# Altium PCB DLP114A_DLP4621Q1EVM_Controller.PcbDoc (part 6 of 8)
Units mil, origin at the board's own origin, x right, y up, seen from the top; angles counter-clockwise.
Board outline 4803.15 x 2598.43 mil, 14 copper layers (Top Layer, GND 1, SIGNAL 1, GND 2, SIGNAL 2, PWR SPLIT PLANE 1, GND 3, GND 4, PWR SPLIT PLANE 2, SIGNAL 3, GND 5, SIGNAL 4, GND 6, Bottom Layer), stack 91.4 mil thick; 489 components, 394 nets, 1925 pads, 1273 vias.
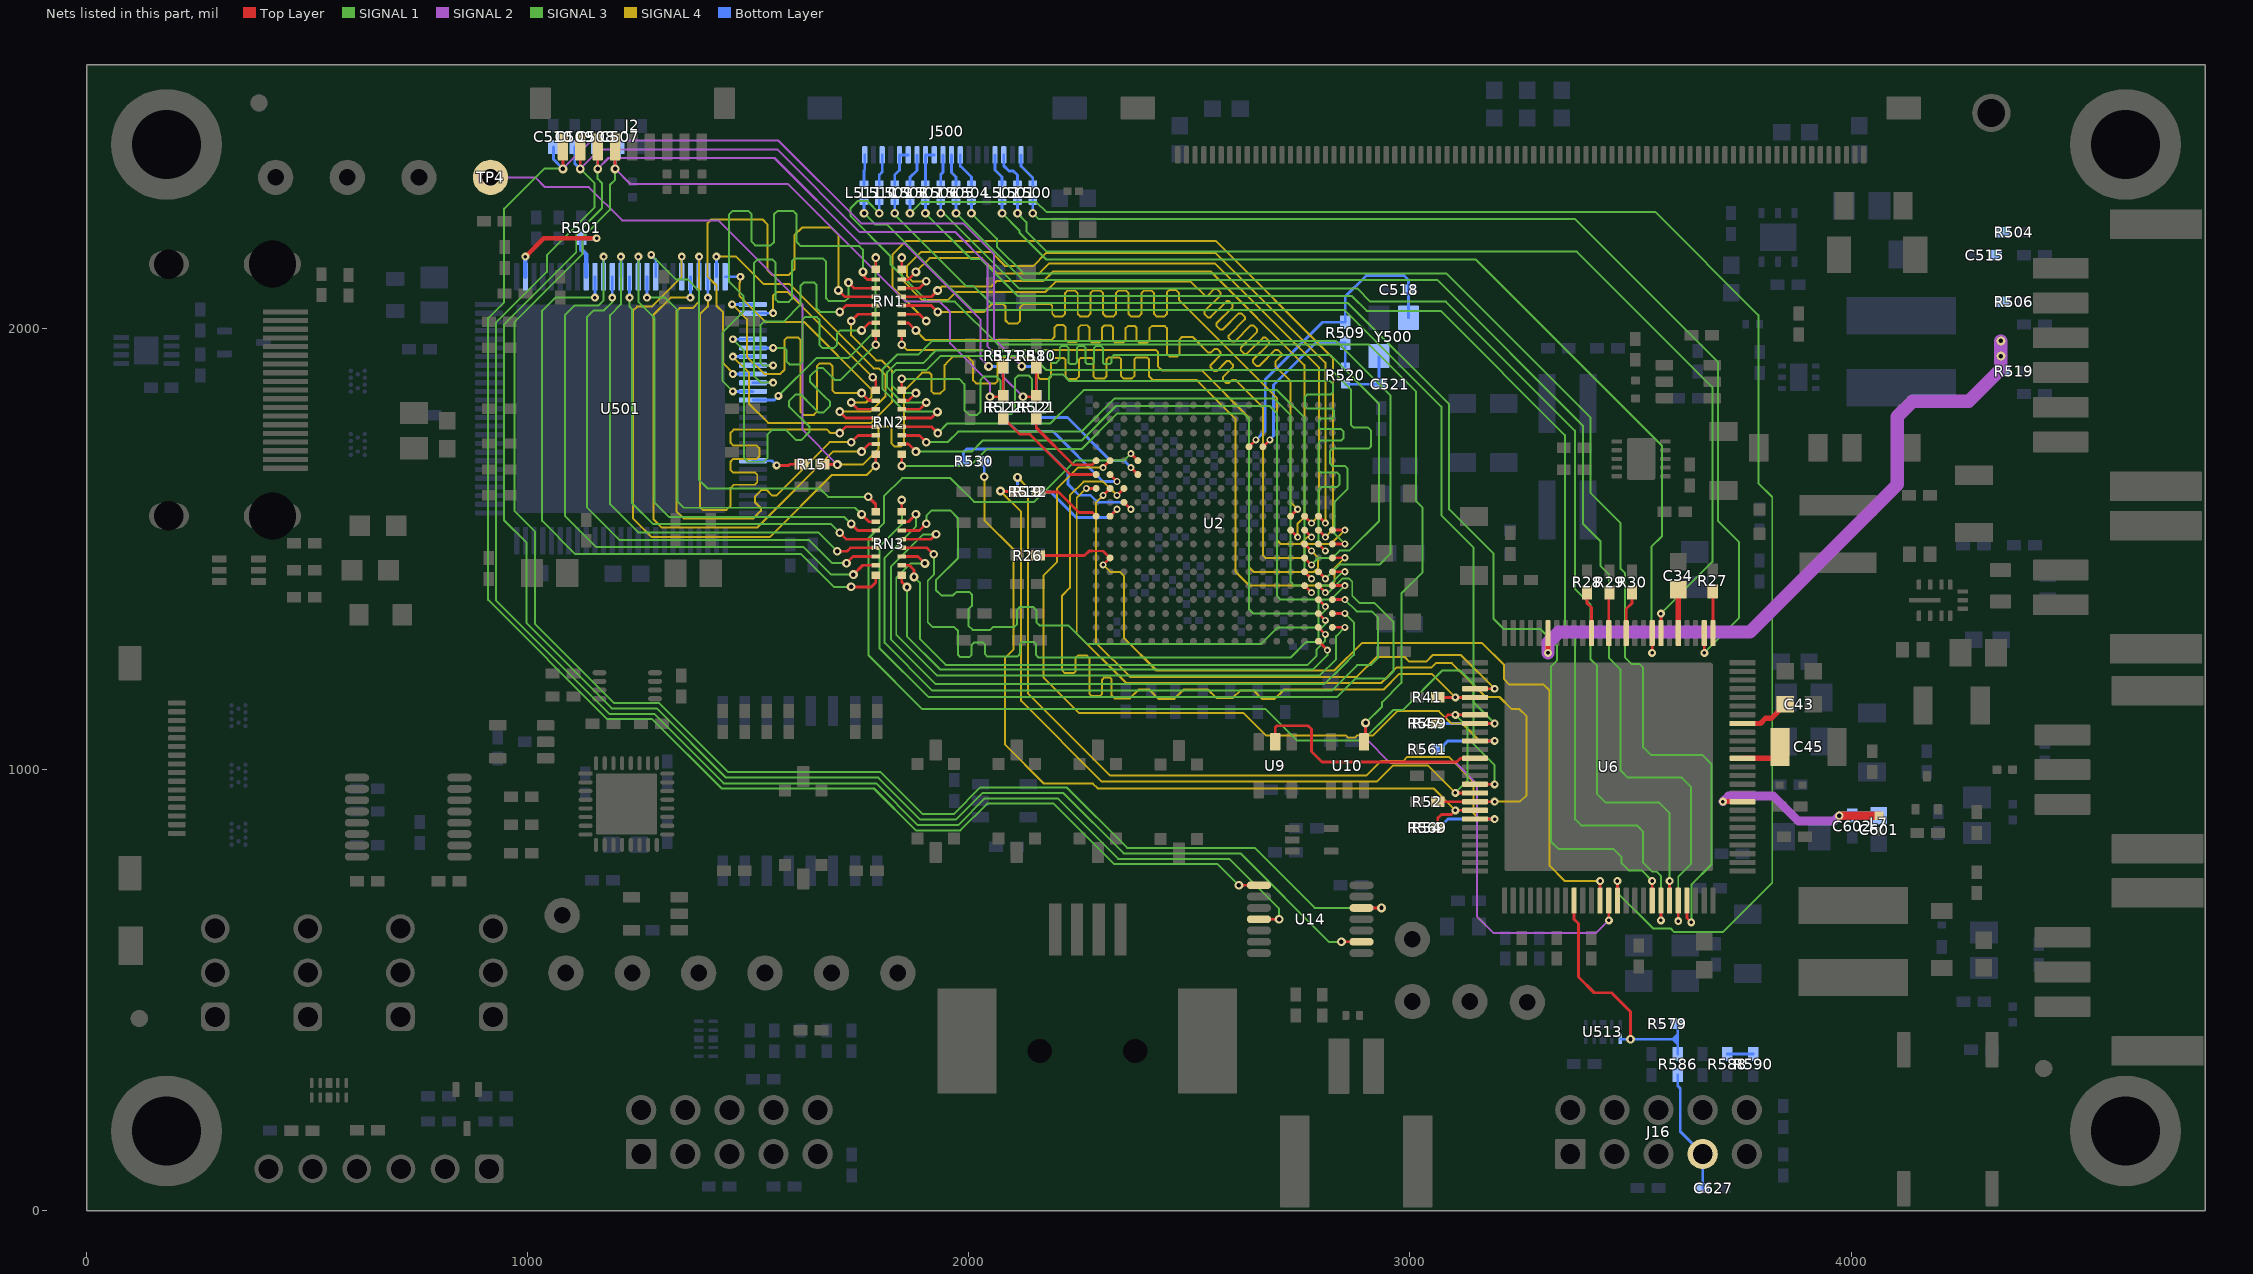
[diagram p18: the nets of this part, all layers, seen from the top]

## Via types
v1: diameter 20, hole 10, Top Layer to Bottom Layer, tented top, 716 vias
v2: diameter 16, hole 8, Top Layer to Bottom Layer, 234 vias
v3: diameter 19.68, hole 7.87, Top Layer to Bottom Layer, 170 vias
v4: diameter 18, hole 8, Top Layer to Bottom Layer, tented top, 78 vias
v5: diameter 18, hole 8, Top Layer to Bottom Layer, tented bottom, 51 vias
v6: diameter 39.37, hole 19.68, Top Layer to Bottom Layer, 24 vias

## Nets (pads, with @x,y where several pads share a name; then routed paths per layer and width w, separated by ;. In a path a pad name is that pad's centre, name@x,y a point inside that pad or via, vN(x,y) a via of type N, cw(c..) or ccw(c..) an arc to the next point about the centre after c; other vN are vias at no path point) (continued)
PCLK: R15.2 TP4.1 U2.M18 | length 3706.6
  Top Layer w6.3: R15.2@1667.85,1692.37 1668.18,1692.04 1701.77,1692.04 v1(1702.1,1691.71) ; U2.M18@2824.17,1480.31 v2@2852.33,1480.31
  SIGNAL 4 w4.5: v1(1702.1,1691.71) 1759.51,1691.71 1794.76,1726.96 1794.76,1773.77 1799.44,1778.45 1821.7,1778.45 1825.11,1775.05 1825.11,1738.96 1831.71,1732.35 1845.94,1732.35 1852.43,1738.84 1852.43,1858.4 1894.14,1900.11 1910.66,1900.11 1914.88,1895.89 1914.88,1858.36 1920.21,1853.03 1935.52,1853.03 1944.86,1862.37 1944.86,1917.34 1952.43,1924.91 1963.98,1936.46 1997.13,1936.46 2002.72,1930.87 2009.63,1923.97 2009.63,1882.65 2016.57,1875.71 2050.69,1875.71 2060.24,1875.71 2065.21,1880.68 2065.21,1924.65 2074.88,1934.32 2150.85,1934.32 2152.79,1932.38 2156.45,1928.72 2156.45,1890.36 2161.47,1885.34 2180.91,1885.34 2186.22,1890.66 2186.22,1928.83 2190.31,1932.92 2215.72,1932.92 2219.38,1929.26 2219.38,1890.9 2224.39,1885.89 2243.84,1885.89 2249.15,1891.2 2249.15,1929.37 2253.24,1933.46 2278.64,1933.46 2282.3,1929.8 2282.3,1891.44 2287.32,1886.43 2306.77,1886.43 2312.08,1891.74 2312.08,1929.91 2316.17,1934 2341.57,1934 2345.23,1930.34 2345.23,1891.98 2350.25,1886.97 2369.69,1886.97 2375,1892.28 2375,1930.45 2379.09,1934.54 2404.5,1934.54 2408.16,1930.89 2408.16,1892.52 2417.49,1883.19 2516.83,1883.19 2518.05,1881.97 2603.97,1796.05 2603.97,1449.35 2636.16,1417.16 2819.43,1417.16 2829.38,1427.11 2829.38,1457.34 v2(2852.49,1480.48)
  SIGNAL 2 w4.5: TP4.1@915.73,2342.8 1017.24,2342.8 1039.18,2320.86 1138.56,2320.86 1214.12,2245.3 1431.9,2245.3 1622.97,2054.23 1622.97,1770.84 v1(1702.1,1691.71)
PCLK_S: R15.1 U501.44 | length 115.4
  Top Layer w6.3: v5(1564.12,1689.81) 1592.46,1689.81 1595.02,1692.37 R15.1@1620.61,1692.37
  Bottom Layer w6.3: U501.44@1510.53,1700.21 1553.72,1700.21 v5(1564.12,1689.81)
PDATA0: RN3.9 U2.V17 | length 1180.5
  Top Layer w6.3: RN3.9@1847.91,1440.45 1847.91,1425.89 v1(1859.71,1414.09) ; U2.V17@2792.51,1291.17 v2(2812.56,1271.12)
  SIGNAL 1 w4.5: v1@1859.39,1413.77 1859.39,1302.96 1935.71,1226.64 2779.79,1226.64 2812.56,1259.41 v2(2812.56,1271.12)
PDATA1: RN3.10 U2.U17 | length 1205.5
  Top Layer w6.3: RN3.10@1847.91,1463.51 1865.11,1463.51 1875.63,1452.99 v1(1875.63,1437.04) ; U2.U17@2792.51,1322.67 v2(2808.26,1306.9)
  SIGNAL 1 w4.5: v1(1875.63,1437.04) 1888.79,1423.87 1888.79,1296.64 1947.54,1237.89 2768.19,1237.89 2788.4,1258.09 2788.4,1273.03 2807.52,1292.15 2807.52,1306.16 v2(2808.26,1306.9)
PDATA2: RN3.11 U2.U18 | length 1426.2
  Top Layer w6.3: RN3.11@1847.91,1483.27 1884.76,1483.27 v1(1900.33,1467.7) ; U2.U18@2824.13,1322.79 v2(2852.49,1322.79)
  SIGNAL 1 w4.5: v1(1900.33,1467.7) 1867.85,1467.7 1835.42,1435.27 1835.42,1305.48 1927.22,1213.69 2795.49,1213.69 2832.53,1250.73 2832.53,1302.84 v2(2852.49,1322.79)
PDATA3: RN3.12 U2.T17 | length 1385.3
  Top Layer w6.3: RN3.12@1847.91,1502.95 1905.5,1502.95 v1@1920.09,1488.37 ; U2.T17@2792.51,1354.16 v2(2808.26,1338.42)
  SIGNAL 1 w4.5: v1(1920.45,1488.37) 1920.45,1442.37 1906.81,1428.73 1906.81,1334.37 1917.32,1323.86 1966.13,1323.86 1975.59,1314.4 1975.59,1260.09 1980.67,1255.01 2000.89,1255.01 2006.31,1260.42 2006.31,1282.76 2012.13,1288.58 2030.91,1288.58 2036.71,1282.79 2036.71,1261.73 2042.06,1256.38 2109.97,1256.38 2115.85,1262.26 2115.85,1284.56 2121.28,1289.98 2147.12,1289.98 2152.29,1284.82 2152.29,1259.74 2157.92,1254.11 2729.1,1254.11 2764.01,1289.01 2784.31,1289.01 2792.42,1297.12 2792.42,1314.25 2808.26,1330.08 v2(2808.26,1338.42)
PDATA4: RN3.13 U2.T18 | length 1629
  Top Layer w6.3: RN3.13@1847.91,1522.64 1914.83,1522.64 v1@1925.71,1533.51 ; U2.T18@2824.13,1354.29 v2(2852.49,1354.29)
  SIGNAL 1 w4.5: v1(1925.77,1533.58) 1925.64,1533.45 1896.27,1533.45 1823.86,1461.04 1823.86,1294.73 1924.23,1194.36 2806.6,1194.36 2848.47,1236.24 2872.75,1260.51 2872.75,1334.03 v2(2852.49,1354.29)
PDATA5: RN3.14 U2.R17 | length 1489.9
  Top Layer w6.3: RN3.14@1847.91,1542.32 1888.08,1542.32 v1(1903.53,1557.77) ; U2.R17@2792.51,1385.66 v2(2808.26,1369.91)
  SIGNAL 1 w4.5: v1(1903.53,1557.77) 1903.53,1575.8 1915.58,1587.85 1957.4,1587.85 1975.4,1569.84 1975.4,1479.39 1925.3,1429.28 1925.3,1407.35 1937.56,1395.09 1964.1,1395.09 1972.33,1403.31 2000.83,1403.31 2006.94,1397.2 2006.94,1371.5 1998.96,1363.52 1998.96,1326.41 2008.44,1316.93 2048.3,1316.93 2055.19,1323.81 2103.39,1323.81 2109.68,1330.1 2109.68,1362.57 2115.95,1368.83 2146.1,1368.83 2153.01,1361.92 2153.01,1334.4 2160.1,1327.31 2225.62,1327.31 2267.49,1285.44 2663.08,1285.44 2700.52,1322.87 2784.89,1322.87 2792.51,1330.49 2792.51,1345.94 2808.26,1361.69 v2(2808.26,1369.91)
PDATA6: RN3.15 U2.R18 | length 1765.1
  Top Layer w6.3: RN3.15@1847.91,1562.01 1862.8,1562.01 v1(1879.83,1579.04) ; U2.R18@2824.13,1385.79 v2(2852.49,1385.79)
  SIGNAL 1 w4.5: v1@1879.94,1578.94 1879.94,1551.14 1809.17,1480.38 1809.17,1287.53 1917.37,1179.33 2822.52,1179.33 2880.15,1236.96 2911.29,1236.96 2927.1,1252.77 2927.1,1345.34 2913.62,1358.82 2879.31,1358.82 v2@2852.49,1385.63
PDATA7: RN3.16 U2.P17 | length 1979.6
  Top Layer w6.3: RN3.16@1847.91,1585.14 v1(1847.91,1611.51) ; U2.P17@2792.51,1417.16 v2(2808.26,1401.41)
  SIGNAL 1 w4.5: v1(1847.91,1611.51) 1847.91,1556.1 1797.23,1505.42 1797.23,1275.96 1908.89,1164.3 2833.58,1164.3 2875.94,1206.65 2946.27,1206.65 2962.26,1222.64 2962.26,1335.55 2919.37,1378.44 2885.07,1378.44 2879.39,1384.11 2869.13,1394.38 2869.13,1426.11 2862.22,1433.03 2846.56,1433.03 2814.93,1401.41 v2(2808.26,1401.41)
PDATA8: RN2.9 U2.P18 | length 1583.7
  Top Layer w6.3: v1(1847.91,1688.76) RN2.9@1847.91,1715.12 ; U2.P18@2824.13,1417.28 v2(2852.49,1417.28)
  SIGNAL 1 w4.5: v1@1848.08,1688.93 2003.27,1688.93 2041.02,1726.68 2229.36,1726.68 2255.32,1726.68 2336.22,1807.58 2622.51,1807.58 2635.03,1795.06 2635.03,1364.09 2644.96,1354.16 2786.56,1354.16 2792.51,1360.12 2792.51,1375.85 2802.32,1385.66 2820.68,1385.66 v2@2852.31,1417.28
PDATA9: RN2.10 U2.N18 | length 1544.5
  Top Layer w6.3: RN2.10@1847.91,1738.25 1862.8,1738.25 v1(1879.83,1721.22) ; U2.N18@2824.13,1448.78 v2(2852.49,1448.78)
  SIGNAL 1 w4.5: v1(1879.83,1721.22) 2006.46,1721.22 2031.56,1746.32 2229.36,1746.32 2255.47,1746.32 2333.61,1824.47 2682.19,1824.47 2698.02,1808.64 2698.02,1394.85 2707.21,1385.66 2786.56,1385.66 2792.51,1391.61 2792.51,1411.2 2798.51,1417.2 2815.71,1417.2 2847.29,1448.78 v2(2852.49,1448.78)
PDATA10: RN2.11 U2.P16 | length 1402.1
  Top Layer w6.3: RN2.11@1847.91,1757.94 1888.08,1757.94 v1(1903.53,1742.49) ; U2.P16@2761.01,1417.16 v2(2776.76,1401.41)
  SIGNAL 1 w4.5: v1(1903.53,1742.49) 1951.54,1742.49 1975.68,1766.64 2229.36,1766.64 2255.38,1766.64 2330.51,1841.77 2690.81,1841.77 2729.52,1803.05 2729.52,1425.69 2738,1417.21 2760.96,1417.21 v2(2776.76,1401.41)
PDATA11: RN2.12 U2.N16 | length 1379.3
  Top Layer w6.3: RN2.12@1847.91,1777.62 1914.83,1777.62 v1(1929.42,1763.04) ; U2.N16@2761.01,1448.65 v2(2776.76,1432.9)
  SIGNAL 1 w4.5: v1(1929.42,1763.04) 1951.19,1784.81 2184.28,1784.81 2229.36,1829.88 2259.95,1860.48 2698.51,1860.48 2761.01,1797.97 2761.01,1448.65 v2(2776.76,1432.9)
PDATA12: RN2.13 U2.N17 | length 2058.3
  Top Layer w6.3: RN2.13@1847.91,1797.31 1914.83,1797.31 v1(1928.68,1811.16) ; U2.N17@2792.51,1448.65 v2(2808.26,1432.9)
  SIGNAL 1 w4.5: v1(1928.68,1811.16) 1927.94,1811.9 1855.24,1811.9 1804.56,1862.57 1804.56,1908.36 1837.09,1940.88 1885.4,1940.88 1916.14,1971.63 2832.6,1971.63 2955.74,1848.48 2955.74,1489.47 2931.5,1465.23 2840.58,1465.23 v2(2808.26,1432.9)
PDATA13: RN2.14 U2.M16 | length 2122.9
  Top Layer w6.3: RN2.14@1847.91,1816.99 1888.08,1816.99 v1(1903.53,1832.44) ; U2.M16@2761.01,1480.15 v2(2776.76,1464.4)
  SIGNAL 1 w4.5: v1(1903.53,1832.44) 1849.4,1832.44 1814.96,1866.88 1814.96,1901.26 1836.1,1922.39 1897.41,1922.39 1925.49,1950.48 2176.86,1950.48 2183.66,1943.67 2183.66,1927.75 2189.02,1922.39 2198.38,1922.39 2206.06,1930.07 2206.06,1956.09 2209.96,1959.99 2221.66,1959.99 2225.56,1956.09 2225.56,1923.17 2229.46,1919.27 2241.16,1919.27 2245.06,1923.17 2245.06,1956.09 2248.96,1959.99 2260.66,1959.99 2264.56,1956.09 2264.56,1923.17 2268.46,1919.27 2280.16,1919.27 2284.06,1923.17 2284.06,1956.09 2287.96,1959.99 2299.66,1959.99 2303.56,1956.09 2303.56,1923.17 2307.46,1919.27 2319.16,1919.27 2323.06,1923.17 2323.06,1934.32 2328.32,1939.58 2374.09,1939.58 ; 2387.23,1939.58 2374.09,1939.58 ; v2(2776.76,1464.4) 2792.35,1479.99 2823.85,1479.99 2840.38,1496.52 2862.5,1496.52 2929.73,1563.75 2929.73,1829.75 2819.9,1939.58 2374.09,1939.58
PDATA14: RN2.15 U2.L18 | length 1774.7
  Top Layer w6.3: RN2.15@1847.91,1836.68 1862.8,1836.68 v1(1879.83,1853.71) ; U2.L18@2824.13,1511.77 v2(2852.49,1511.77)
  SIGNAL 1 w4.5: v1(1879.83,1853.71) 1843.64,1853.71 1825.48,1871.88 1825.48,1897.05 1834.79,1906.36 1904.16,1906.36 1935.2,1937.41 2143.84,1937.41 2174.88,1906.36 2184.93,1906.36 ; 2184.95,1906.38 2217.22,1906.38 ; 2217.23,1906.36 2821.71,1906.36 2865.95,1862.12 2865.95,1781.83 2872.4,1775.38 2905.28,1775.38 2912.08,1768.58 2912.08,1733.79 2906.19,1727.9 2823.81,1727.9 2818.24,1722.33 2818.24,1694.26 2823.48,1689.01 2852.01,1689.01 2858.75,1682.28 2858.75,1636.48 2828.4,1606.14 2828.4,1535.86 v2(2852.49,1511.77)
PDATA15: RN2.16 U2.L17 | length 2202.8
  Top Layer w6.3: RN2.16@1847.91,1859.81 v1(1847.91,1886.18) ; U2.L17@2792.51,1511.64 v2(2808.26,1495.9)
  SIGNAL 1 w4.5: v1(1847.91,1886.18) 1939.27,1886.18 1977.82,1886.18 1989.99,1874 1989.99,1815.3 2001.04,1804.24 2018.9,1804.24 2026.67,1812.01 2026.67,1883.84 2034.24,1891.42 2062.43,1891.42 2071.9,1881.95 2071.9,1812.62 2077.74,1806.77 2096.65,1806.77 2104.17,1814.29 2104.17,1886.12 2111.75,1893.7 2135.41,1893.7 2142.92,1886.18 2142.92,1816.63 2150.5,1809.05 2174.16,1809.05 2181.68,1816.57 2181.68,1888.4 2189.25,1895.98 2212.91,1895.98 2228.13,1880.76 2818.89,1880.76 2825.2,1874.45 2825.2,1855.85 2819.86,1850.51 2766.96,1850.51 2762.28,1845.83 2762.28,1823.8 2767.46,1818.62 2823.45,1818.62 2827.45,1814.61 2827.45,1799.48 2823.78,1795.81 2797.47,1795.81 2793.53,1791.87 2793.53,1776.53 2797.97,1772.09 2843.93,1772.09 2849.09,1766.93 2849.09,1751.29 2844.31,1746.51 2798.28,1746.51 2792.32,1740.54 2792.32,1679.63 2797.73,1674.21 2834.16,1674.21 2839.91,1668.46 2839.91,1646.09 2834.43,1640.61 2798.32,1640.61 2792.32,1634.61 2792.32,1511.84 v2(2808.26,1495.9)
PDATA16: RN1.9 U2.L16 | length 1471.8
  Top Layer w6.3: v1(1847.91,1963.43) RN1.9@1847.91,1989.79 ; U2.L16@2761.01,1511.64 v2(2776.76,1495.9)
  SIGNAL 4 w4.5: v1(1847.91,1963.43) 1859.57,1951.72 2423.65,1951.72 2429.25,1946.11 2429.25,1913.97 2437.83,1905.39 2527.49,1905.39 2635.03,1797.85 2635.03,1458.58 2645.27,1448.34 2782.27,1448.34 2792.01,1458.08 2792.01,1480.65 v2(2776.76,1495.9)
PDATA17: RN1.10 U2.K18 | length 2012.4
  Top Layer w6.3: RN1.10@1847.91,2012.92 1862.8,2012.92 v1(1879.83,1995.89) ; U2.K18@2824.13,1543.27 v2(2852.49,1543.27)
  SIGNAL 4 w4.5: v1(1879.83,1995.89) 1901.69,1974.03 2186.54,1974.03 2194.52,1982.01 2194.52,2002.61 2200.05,2008.14 2214.48,2008.14 2219.54,2003.08 2219.54,1974.43 2224.81,1969.17 2243.01,1969.17 2248.19,1974.34 2248.19,2002.02 2253.72,2007.55 2268.14,2007.55 2273.2,2002.49 2273.2,1973.84 2278.47,1968.58 2296.67,1968.58 2301.85,1973.75 2301.85,2001.43 2307.38,2006.96 2321.8,2006.96 2326.87,2001.9 2326.87,1973.25 2332.14,1967.99 2350.33,1967.99 2355.51,1973.16 2355.51,2000.84 2361.04,2006.37 2375.46,2006.37 2380.53,2001.31 2380.53,1972.66 2385.8,1967.4 2404,1967.4 2409.17,1972.57 2409.17,2000.25 2414.7,2005.78 2444.12,2005.78 2449.19,2000.72 2449.19,1942.07 2454.46,1936.81 2472.66,1936.81 2477.83,1941.98 2477.83,1975.57 2483.16,1980.9 2507.52,1980.9 2542.98,1945.44 2548.49,1945.44 2557.12,1954.06 2562.64,1954.06 2570.91,1945.79 2570.91,1940.28 2548.14,1917.51 2548.14,1911.99 2556.41,1903.72 2561.93,1903.72 2584.7,1926.49 2590.21,1926.49 2598.49,1918.21 2598.49,1912.7 2575.72,1889.93 2575.72,1884.41 2583.99,1876.14 2589.51,1876.14 2596.71,1883.34 2605.07,1883.34 2666.52,1821.9 2666.52,1485.99 2672.35,1480.15 2754.79,1480.15 2761.01,1486.37 2761.01,1503.19 2769.47,1511.64 2820.87,1511.64 v2(2852.49,1543.27)
PDATA18: RN1.11 U2.K17 | length 1801.2
  Top Layer w6.3: RN1.11@1847.91,2032.61 1888.08,2032.61 v1(1903.53,2017.16) ; U2.K17@2792.51,1543.14 v2(2808.26,1527.39)
  SIGNAL 4 w4.5: v1(1903.53,2017.16) 1827.02,2093.67 1827.02,2168.24 1857.7,2198.92 2559.8,2198.92 2825.39,1933.33 2825.39,1881.97 2825.39,1544.52 v2(2808.26,1527.39)
PDATA19: RN1.12 U2.K16 | length 1970.7
  Top Layer w6.3: RN1.12@1847.91,2052.29 1914.83,2052.29 v1(1929.42,2037.7) ; U2.K16@2761.01,1543.14 v2(2776.76,1527.39)
  SIGNAL 4 w4.5: v1(1929.42,2037.7) 1958.06,2037.7 2034.3,2037.7 2052.02,2055.43 2078.06,2055.43 2083.11,2050.37 2083.11,2018.34 2090.3,2011.15 2109.7,2011.15 2115.58,2017.03 2115.58,2047.14 2122.63,2054.2 2124.29,2055.85 2184.69,2055.85 2189.04,2051.5 2189.04,2033.25 ; 2189.04,2033.18 2194.35,2027.87 2212.76,2027.87 2218.01,2033.12 ; 2218.01,2033.2 2218.01,2080.53 ; 2218.01,2080.68 2218.01,2080.53 ; 2246.86,2033.05 2252.04,2027.87 2270.45,2027.87 2275.7,2033.12 ; 2246.86,2033.12 2246.86,2080.6 2241.68,2085.78 2223.27,2085.78 2218.01,2080.53 ; 2275.7,2033.2 2275.7,2080.53 ; 2275.7,2080.68 2275.7,2080.53 ; 2304.54,2033.05 2309.72,2027.87 2328.14,2027.87 2333.39,2033.12 ; 2304.54,2033.12 2304.54,2080.6 2299.37,2085.78 2280.95,2085.78 2275.7,2080.53 ; 2333.39,2033.2 2333.39,2080.53 ; 2333.39,2080.68 2333.39,2080.53 ; 2362.23,2033.05 2367.41,2027.87 2385.82,2027.87 2391.07,2033.12 ; 2362.23,2033.12 2362.23,2080.6 2357.05,2085.78 2338.64,2085.78 2333.39,2080.53 ; 2391.07,2033.2 2391.07,2080.53 2396.33,2085.78 2414.74,2085.78 2419.92,2080.6 2419.92,2033.12 2425.17,2027.87 2443.58,2027.87 2448.76,2033.05 2448.76,2082.3 2453.67,2087.21 2469.77,2087.21 2476.03,2080.95 2476.03,2065.16 2659.21,1881.97 2698.02,1843.16 2698.02,1520.9 2707.27,1511.64 2751.65,1511.64 2767.4,1527.39 v2(2776.76,1527.39)
PDATA20: RN1.13 U2.K15 | length 1442.7
  Top Layer w6.3: RN1.13@1847.91,2071.98 1914.83,2071.98 v1(1929.23,2086.38) ; U2.K15@2729.52,1543.14 v2(2745.27,1527.39)
  SIGNAL 4 w4.5: v1(1929.23,2086.38) 1938.21,2095.36 2050.47,2095.36 2062.63,2107.52 2169.15,2107.52 2191.01,2129.38 2548.37,2129.38 2760.62,1917.12 2760.62,1881.97 2760.62,1572.69 2745.06,1557.13 v2@2745.06,1527.6
PDATA21: RN1.14 U2.J17 | length 1609.6
  Top Layer w6.3: RN1.14@1847.91,2091.66 1888.08,2091.66 v1(1903.53,2107.11) ; U2.J17@2792.51,1574.64 v2(2808.26,1558.89)
  SIGNAL 4 w4.5: v1(1903.53,2107.11) 1871.92,2107.11 1859.6,2119.43 1859.6,2141.54 1892.08,2174.02 2050.66,2174.02 2083.07,2141.6 2145.55,2141.6 2174.78,2170.83 2560.09,2170.83 2808.26,1922.66 2808.26,1881.97 v2(2808.26,1558.89)
PDATA22: RN1.15 U2.J16 | length 1468.4
  Top Layer w6.3: RN1.15@1847.91,2111.35 1862.8,2111.35 v1(1879.83,2128.38) ; U2.J16@2761.01,1574.64 v2(2776.76,1558.89)
  SIGNAL 4 w4.5: v1(1879.83,2128.38) 1910.99,2159.54 2029.53,2159.54 2063.65,2125.41 2159.51,2125.41 2181.76,2147.66 2557.48,2147.66 2793.22,1911.92 2793.22,1881.97 2793.22,1575.35 v2(2776.76,1558.89)
PDATA23: RN1.16 U2.J15 | length 2009.9
  Top Layer w6.3: RN1.16@1847.91,2134.48 v1(1847.91,2160.84) ; U2.J15@2729.52,1574.64 v2(2745.27,1590.38)
  SIGNAL 4 w4.5: v1(1847.91,2160.84) 1847.91,2111.52 1894.77,2064.66 1952.06,2064.66 1969.91,2082.51 2172.66,2082.51 2196.8,2106.65 2503.03,2106.65 2535.55,2074.12 2541.07,2074.12 2556.77,2089.82 2562.28,2089.82 2570.55,2081.55 2570.55,2076.03 2533.64,2039.12 2533.64,2033.61 2541.92,2025.33 2547.43,2025.33 2584.34,2062.24 2589.86,2062.24 2598.13,2053.97 2598.13,2048.45 2561.22,2011.54 2561.22,2006.03 2569.49,1997.76 2575.01,1997.76 2611.92,2034.67 2617.44,2034.67 2625.71,2026.39 2625.71,2020.88 2588.8,1983.97 2588.8,1978.45 2597.07,1970.18 2602.59,1970.18 2639.5,2007.09 2645.01,2007.09 2653.29,1998.82 2653.29,1993.3 2616.38,1956.39 2616.38,1950.87 2624.65,1942.6 2630.16,1942.6 2667.08,1979.51 2672.59,1979.51 2680.86,1971.24 2680.86,1965.72 2643.95,1928.81 2643.95,1923.3 2652.23,1915.02 2657.74,1915.02 2694.65,1951.93 2700.17,1951.93 2708.44,1943.66 2708.44,1938.15 2694.9,1924.61 2694.9,1914.78 2729.52,1880.16 2729.52,1606.13 v2(2745.27,1590.38)
PDATA_S0: RN3.8 U501.10 | length 1493.6
  Top Layer w6.3: v1@1733.26,1414.5 1778.82,1414.5 1788.85,1424.54 RN3.8@1788.85,1440.45
  SIGNAL 1 w4.5: v5(1152.26,2070.34) 1062.5,2070.34 1032.63,2040.48 1032.63,1564.25 1108.01,1488.88 1619.58,1488.88 1693.88,1414.58 v1(1733.18,1414.58)
  Bottom Layer w6.3: v5(1152.26,2070.34) U501.10@1152.26,2117.53
PDATA_S1: RN3.7 U501.11 | length 1469.6
  Top Layer w6.3: v1(1738.18,1442.39) 1759.37,1463.58 RN3.7@1788.85,1463.58
  SIGNAL 1 w4.5: v5@1172.03,2162.94 1172.03,2063.9 1160.21,2052.08 1105.86,2052.08 1084.4,2030.62 1084.4,1575.21 1154.99,1504.62 1625.71,1504.62 1687.94,1442.39 v1(1738.18,1442.39)
  Bottom Layer w6.3: U501.11@1171.95,2117.53 v5(1171.95,2163.02)
PDATA_S2: RN3.6 U501.12 | length 1273.4
  Top Layer w6.3: v1(1722.57,1468.14) 1737.7,1483.27 RN3.6@1788.85,1483.27
  SIGNAL 1 w4.5: v5(1191.63,2070.34) 1191.63,2060.03 1172.89,2041.29 1149.44,2041.29 1134.59,2026.44 1134.59,1594.32 1208.61,1520.3 1637.86,1520.3 1690.02,1468.14 v1(1722.57,1468.14)
  Bottom Layer w6.3: v5(1191.63,2070.34) U501.12@1191.63,2117.53
PDATA_S3: RN3.5 U501.13 | length 1266
  Top Layer w6.3: v1(1701.48,1495.31) 1723.83,1495.31 1731.48,1502.95 RN3.5@1788.85,1502.95
  SIGNAL 1 w4.5: v5(1211.32,2163.02) 1211.3,2054.82 1187.05,2030.57 1187.05,1601.44 1250.2,1538.29 1658.5,1538.29 v1(1701.48,1495.31)
  Bottom Layer w6.3: U501.13@1211.32,2117.53 v5(1211.32,2163.02)
PDATA_S4: RN3.4 U501.14 | length 1101.6
  Top Layer w6.3: v1(1707.34,1537.23) 1721.93,1522.64 RN3.4@1788.85,1522.64
  SIGNAL 1 w4.5: v5(1231,2070.34) 1231,2049.39 1236.43,2043.96 1236.43,1604.55 1284.25,1556.73 1687.84,1556.73 v1(1707.34,1537.23)
  Bottom Layer w6.3: v5(1231,2070.34) U501.14@1231,2117.53
PDATA_S5: RN3.3 U501.15 | length 1145.6
  Top Layer w6.3: v1(1733.24,1557.34) 1748.25,1542.32 RN3.3@1788.85,1542.32
  SIGNAL 1 w4.5: v5(1250.69,2163.02) 1250.69,2060.97 1287.29,2024.36 1287.29,1605.98 1320.84,1572.43 1718.14,1572.43 v1(1733.24,1557.34)
  Bottom Layer w6.3: U501.15@1250.69,2117.53 v5(1250.69,2163.02)
PDATA_S6: RN3.2 U501.16 | length 1030.6
  Top Layer w6.3: v1(1756.93,1578.83) 1773.67,1562.09 RN3.2@1788.85,1562.09
  SIGNAL 1 w4.5: v5(1270.37,2070.34) 1311.65,2070.34 1340.02,2041.98 1340.02,1607.68 1353.84,1593.86 1741.9,1593.86 v1(1756.93,1578.83)
  Bottom Layer w6.3: v5(1270.37,2070.34) U501.16@1270.37,2117.53
PDATA_S7: RN3.1 U501.17 | length 1064.1
  Top Layer w6.3: v1(1771.85,1618.85) 1788.85,1601.84 RN3.1@1788.85,1585.14
  SIGNAL 1 w4.5: v5(1280.06,2167.05) 1335.63,2111.47 1362.46,2111.47 1388.14,2085.8 1388.14,1657.43 1408.14,1637.43 1662.16,1637.43 1680.99,1618.6 v1@1771.61,1618.6
  Bottom Layer w6.3: v5(1280.06,2167.05) 1290.06,2157.05 U501.17@1290.06,2117.53
PDATA_S8: RN2.8 U501.20 | length 1364.9
  Top Layer w6.3: v1(1788.85,1688.76) RN2.8@1788.85,1715.12
  SIGNAL 4 w4.5: v5(1349.11,2163.02) 1349.11,2117.56 1281.55,2050 1248.08,2050 1238.58,2040.49 1238.58,1569.56 1280.29,1527.85 1549.35,1527.85 1689.58,1668.08 1768.18,1668.08 v1(1788.85,1688.76)
  Bottom Layer w6.3: U501.20@1349.11,2117.53 v5(1349.11,2163.02)
PDATA_S9: RN2.7 U501.21 | length 1200.7
  Top Layer w6.3: v1(1756.93,1721.22) 1773.97,1738.25 RN2.7@1788.85,1738.25
  SIGNAL 4 w4.5: v5(1368.8,2070.34) 1324.07,2070.34 1285.13,2031.41 1285.13,1567.51 1303.65,1548.99 1519.7,1548.99 1691.92,1721.22 v1(1756.93,1721.22)
  Bottom Layer w6.3: v5(1368.8,2070.34) U501.21@1368.8,2117.53
PDATA_S10: RN2.6 U501.22 | length 1246.3
  Top Layer w6.3: v1(1733.24,1742.49) 1748.68,1757.94 RN2.6@1788.85,1757.94
  SIGNAL 4 w4.5: v5(1388.48,2163.02) 1388.69,2162.81 1388.69,2061.59 1373.68,2046.58 1344.28,2046.58 1337.14,2039.44 1337.14,1586.16 1353.48,1569.83 1511.79,1569.83 1528.72,1586.75 1528.72,1593.23 1515.04,1606.91 1515.04,1619.19 1530.01,1634.16 1541.23,1634.16 1553.98,1621.4 1563.37,1621.4 1684.45,1742.49 v1(1733.24,1742.49)
  Bottom Layer w6.3: U501.22@1388.48,2117.53 v5(1388.48,2163.02)
PDATA_S11: RN2.5 U501.23 | length 1334.9
  Top Layer w6.3: v1(1707.34,1763.04) 1721.93,1777.62 RN2.5@1788.85,1777.62
  SIGNAL 4 w4.5: v5(1408.17,2070.34) 1408.17,2050.45 1390.27,2032.55 1390.27,1595.57 1396.77,1589.07 1450.46,1589.07 1459.96,1598.58 1459.96,1638.51 1467.44,1645.99 1515.05,1645.99 1520.3,1651.24 1520.3,1668.36 1515.4,1673.26 1465.86,1673.26 1459.96,1679.15 1459.96,1698.72 1465.92,1704.68 1519,1704.68 1524.89,1710.58 1524.89,1729.1 1519.18,1734.82 1466.19,1734.82 1459.96,1741.04 1459.96,1763.92 1466.95,1770.91 1678.51,1770.91 1686.38,1763.04 v1(1707.34,1763.04)
  Bottom Layer w6.3: v5(1408.17,2070.34) U501.23@1408.17,2117.53
PDATA_S12: RN2.4 U501.24 | length 793.4
  Top Layer w6.3: v1(1707.34,1811.9) 1721.93,1797.31 RN2.4@1788.85,1797.31
  SIGNAL 4 w4.5: v5(1427.85,2163.02) 1472.49,2163.02 1534.08,2101.43 1592.78,2101.43 1784.2,1910.01 1795.97,1910.01 1810.59,1895.39 1810.59,1846.02 1776.46,1811.9 v1(1707.34,1811.9)
  Bottom Layer w6.3: U501.24@1427.85,2117.53 v5(1427.85,2163.02)
PDATA_S13: RN2.3 U501.25 | length 596.1
  Top Layer w6.3: v1(1733.24,1832.44) 1748.68,1816.99 RN2.3@1788.85,1816.99
  SIGNAL 4 w4.5: v5(1482.03,2117.53) 1481.45,2116.94 1481.45,2104.84 1479.9,2103.3 1479.9,2074.37 1538.84,2015.43 1626.3,2015.43 1778.87,1862.86 1778.87,1844.46 1766.86,1832.44 v1(1733.24,1832.44)
  Bottom Layer w6.3: U501.25@1447.54,2117.53 v5(1482.03,2117.53)
PDATA_S14: RN2.2 U501.26 | length 905.8
  Top Layer w6.3: v1(1756.93,1853.71) 1773.97,1836.68 RN2.2@1788.85,1836.68
  SIGNAL 4 w4.5: v5(1463.33,2054.74) 1496.73,2021.34 1496.73,1936.36 1535.86,1897.23 1572.77,1897.23 1581.64,1906.1 1581.64,1973.93 1587.27,1979.56 1613.71,1979.56 1618.31,1974.96 1618.31,1811.54 1625.23,1804.62 1648.54,1804.62 1656.15,1812.23 1656.15,1915.65 1661.81,1921.3 1684.47,1921.3 1690.6,1915.16 1690.6,1860.44 1697.33,1853.71 v1(1756.93,1853.71)
  Bottom Layer w6.3: v5@1463.33,2054.64 1510.43,2054.64 U501.26@1510.53,2054.54
PDATA_S15: RN2.1 U501.27 | length 427.2
  Top Layer w6.3: v1(1782.19,1889.57) 1788.85,1882.9 RN2.1@1788.85,1859.81
  SIGNAL 4 w4.5: v5(1556.05,2034.85) 1556.05,2074.25 1564.6,2082.81 1588.95,2082.81 v1(1782.19,1889.57)
  Bottom Layer w6.3: U501.27@1510.53,2034.85 v5(1556.05,2034.85)
PDATA_S16: RN1.8 U501.30 | length 1081.7
  Top Layer w6.3: v1(1788.85,1963.43) RN1.8@1788.85,1989.79
  SIGNAL 1 w4.5: v5(1465.02,1975.8) 1490.57,1950.25 1490.57,1706.62 1499.05,1698.14 1534.95,1698.14 1543.78,1706.97 1543.78,1760.28 1554.15,1770.65 1585.06,1770.65 1608.69,1747.02 1619.91,1747.02 1638.72,1765.82 1638.72,1777.24 1592.22,1823.74 1592.22,1835.42 1607.63,1850.84 1618.32,1850.84 1647.3,1821.87 1659.7,1809.46 1670.32,1809.46 1685.77,1824.91 1685.77,1833.87 1672.53,1847.1 1639.6,1880.03 1639.6,1891.45 1659.28,1911.12 1668.46,1911.12 1695.67,1883.92 1709.34,1883.92 v1(1788.85,1963.43)
  Bottom Layer w6.3: v5(1465.02,1975.8) U501.30@1510.53,1975.8
PDATA_S17: RN1.7 U501.31 | length 512.2
  Top Layer w6.3: v1(1756.93,1995.89) 1773.97,2012.92 RN1.7@1788.85,2012.92
  SIGNAL 1 w4.5: v5@1555.05,1956.11 1582.08,1956.11 1586.94,1951.25 1586.94,1925.26 1593.43,1918.77 1616.39,1918.77 1622.46,1924.84 1622.46,2020.47 1628.07,2026.07 1655.4,2026.07 1660.92,2020.55 1660.92,1963.43 1668.77,1955.58 1693.76,1955.58 1701.43,1963.25 1701.43,1989.33 1707.99,1995.89 v1(1756.93,1995.89)
  Bottom Layer w6.3: U501.31@1510.53,1956.11 v5(1556.05,1956.11)
PDATA_S18: RN1.6 U501.32 | length 821
  Top Layer w6.3: v1(1733.24,2017.16) 1748.68,2032.61 RN1.6@1788.85,2032.61
  SIGNAL 4 w4.5: v5(1465.02,1936.43) 1501.95,1899.5 1501.95,1829.02 1544.8,1786.17 1778.57,1786.17 1826.16,1833.76 1826.16,1903.91 1802,1928.07 1789.68,1928.07 1733.24,1984.52 v1(1733.24,2017.16)
  Bottom Layer w6.3: v5(1465.02,1936.43) U501.32@1510.53,1936.43
PDATA_S19: RN1.5 U501.33 | length 551.9
  Top Layer w6.3: v1(1707.34,2037.7) 1721.93,2052.29 RN1.5@1788.85,2052.29
  SIGNAL 1 w4.5: v5@1555.05,1916.74 1533.04,1916.74 1528.12,1921.66 1528.12,2008.52 1535.3,2015.7 1579.89,2015.7 1618.88,2054.69 1618.88,2097.7 1625.49,2104.31 1649.94,2104.31 1654.6,2099.65 1654.6,2046.19 1663.08,2037.7 v1(1707.34,2037.7)
  Bottom Layer w6.3: U501.33@1510.53,1916.74 v5(1556.05,1916.74)
PDATA_S20: RN1.4 U501.34 | length 1138.8
  Top Layer w6.3: v1(1704.34,2086.57) 1718.93,2071.98 RN1.4@1788.85,2071.98
  SIGNAL 4 w4.5: v5@1467.36,1897.06 1442.85,1921.57 1442.85,2037.16 1427.89,2052.11 1427.89,2097.67 1407.74,2117.82 1407.74,2239.02 1416.05,2247.33 1532.51,2247.33 1543.37,2236.46 1543.37,2132.28 1554.14,2121.51 1591.99,2121.51 1604.55,2134.07 1604.55,2211.64 1622.02,2229.11 1687.85,2229.11 1704.34,2212.62 v1(1704.34,2086.57)
  Bottom Layer w6.3: v5(1465.02,1897.06) U501.34@1510.53,1897.06
PDATA_S21: RN1.3 U501.35 | length 940.1
  Top Layer w6.3: v1(1727.26,2104.14) 1739.73,2091.66 RN1.3@1788.85,2091.66
  SIGNAL 1 w4.5: v5@1555.05,1877.37 1528.76,1877.37 1512.75,1893.37 1512.75,2148.6 1521.15,2157 1554.54,2157 1561.59,2149.95 1561.59,2066.67 1567.84,2060.43 1592.21,2060.43 1598.91,2067.12 1598.91,2152.29 1605.66,2159.04 1669.25,2159.04 1676.31,2151.99 1676.31,2068.37 1682.44,2062.23 1719.1,2062.23 1727.26,2070.4 v1(1727.26,2104.14)
  Bottom Layer w6.3: U501.35@1510.53,1877.37 v5(1556.05,1877.37)
PDATA_S22: RN1.2 U501.36 | length 1099
  Top Layer w6.3: v1(1759.94,2128.38) 1759.94,2120.84 1769.43,2111.35 RN1.2@1788.85,2111.35
  SIGNAL 1 w4.5: v5(1465.02,1857.69) 1440.99,1881.71 1440.99,1990.74 1489.47,2039.21 1489.47,2072.95 1456.42,2106 1456.42,2258.7 1464.56,2266.83 1499.98,2266.83 1507.36,2259.45 1507.36,2196.91 1515.5,2188.77 1550.92,2188.77 1558.3,2196.16 1558.3,2258.7 1566.44,2266.83 1601.86,2266.83 1609.24,2259.45 1609.24,2196.91 1619.13,2187.03 1751.76,2187.03 1759.94,2178.85 v1(1759.94,2128.38)
  Bottom Layer w6.3: v5(1465.02,1857.69) U501.36@1510.53,1857.69
PDATA_S23: RN1.1 U501.37 | length 535.1
  Top Layer w6.3: RN1.1@1788.85,2134.48 v1(1788.85,2160.84)
  SIGNAL 1 w4.5: v5(1568.33,1847.23) 1654.36,1933.26 1726.36,1933.26 1788.85,1995.75 v1(1788.85,2160.84)
  Bottom Layer w6.3: U501.37@1510.53,1838 1559.1,1838 v5(1568.33,1847.23)
PDZ: R501.1 U501.2 U501.9 | length 351.1
  Top Layer w10: v5(994.78,2163.02) 1036.49,2204.73 v5(1156.38,2204.73)
  Bottom Layer w10: U501.2@994.78,2117.53 v5(994.78,2163.02) ; U501.9@1132.58,2117.53 1132.58,2168.03 1121.46,2179.14 R501.1@1121.46,2204.73 v5(1156.38,2204.73)
PLL_REF_C: C521.1 R520.1 Y500.3 | length 141.6
  Bottom Layer w6.3: R520.1@2853.64,1873.66 C521.1@2930.56,1873.66 2929.59,1874.63 Y500.3@2929.59,1937.95
PLL_REFCLK_I: C518.1 R509.2 U2.D12 Y500.1 | length 714.6
  Top Layer w6.3: U2.D12@2635.03,1732.12 v2(2650.78,1747.86)
  Bottom Layer w6.3: v2(2650.78,1747.86) 2672.01,1769.09 2672.01,1884.93 2801.4,2014.32 R509.2@2853.2,2014.32 2853.2,2072.84 2901,2120.64 2986.15,2120.64 2996.55,2110.24 C518.1@2996.55,2088.43 ; Y500.1@2996.52,2024.57 C518.1@2996.52,2088.43
PLL_REFCLK_O: R509.1 R520.2 U2.D13 | length 405.1
  Top Layer w6.3: U2.D13@2666.53,1732.12 v2(2682.27,1747.86)
  Bottom Layer w6.3: v2(2682.27,1747.86) 2690.81,1756.4 2690.81,1872.3 2785.58,1967.07 R509.1@2853.2,1967.07 2853.42,1966.85 2853.42,1914.24 R520.2@2853.64,1914.02
PMIC_3P3V: C43.1 U6.68 | length 115
  Top Layer w11.8: U6.68@3753.82,1104.74 3794.26,1104.74 3806.16,1116.64 3819.28,1116.64 C43.1@3850.84,1148.2
PMIC_5V: C45.1 U6.64 | length 100.8
  Top Layer w11.6: U6.64@3753.82,1026 3822.36,1026 3838.51,1042.16 C45.1@3838.51,1051.58
PMIC_A3P3V: C34.1 U6.80 | length 98.9
  Top Layer w11.8: U6.80@3608.15,1309.47 C34.1@3608.15,1408.36
PMIC_AD3_PICO: R41.2 U2.G3 U6.5 | length 1830.1
  Top Layer w6.3: v2(2335.82,1621.88) U2.G3@2351.57,1637.63 ; R41.2@3062.87,1163.8 v4(3103,1163.8) U6.5@3147.52,1163.8
  SIGNAL 4 w4.5: v2(2335.82,1621.88) 2304.64,1653.06 2259.99,1653.06 2228.77,1621.84 2228.77,1412.24 2211.4,1394.87 2211.4,1225.48 2217.89,1218.98 2237.87,1218.98 2242.11,1223.22 2242.11,1253.64 2247.58,1259.11 2267.01,1259.11 2273.03,1253.09 2273.03,1172.12 2278.43,1166.72 2297.17,1166.72 2302.25,1171.79 2302.25,1204.27 2307.27,1209.29 2319.5,1209.29 2323.77,1205.02 2323.77,1168.41 2330.3,1161.88 2364.91,1161.88 2384.93,1181.89 2408.61,1181.89 2429.69,1160.8 2465.64,1160.8 2486.72,1181.89 2541.93,1181.89 2561.08,1162.73 2598.74,1162.73 2616.09,1180.09 2645.23,1180.09 2665.2,1160.12 2692.7,1160.12 2714.48,1181.89 2940.09,1181.89 2974.95,1216.75 3050.05,1216.75 v4(3103,1163.8)
PMIC_AD3_POCI: U2.G2 U6.4 | length 1403.8
  Top Layer w6.3: v2(2304.32,1621.88) U2.G2@2320.07,1637.63 ; U6.4@3147.52,1183.48 v4(3192.05,1183.48)
  SIGNAL 4 w4.5: v2(2304.32,1621.88) 2288.63,1606.19 2288.63,1287.12 2365.44,1210.31 2879.72,1210.31 2924.95,1255.54 2987.77,1255.54 2997.7,1245.61 3037.63,1245.61 3052.07,1260.05 3115.49,1260.05 v4(3192.05,1183.48)
PMIC_AD3_SEQ_CLK: R52.2 U2.G1 U6.17 | length 1881.3
  Top Layer w6.3: v2@2266.39,1637.72 U2.G1@2288.48,1637.72 ; R52.2@3062.87,927.58 U6.17@3147.52,927.58 v4(3192.05,927.58)
  SIGNAL 4 w4.5: v2(2266.3,1637.81) 2244.59,1616.1 2244.59,1308.33 2356.42,1196.51 2934.43,1196.51 2970.03,1232.12 3048.87,1232.12 3058.43,1241.67 3094.78,1241.67 3171.57,1164.87 3202.91,1164.87 3230.62,1137.17 3248.25,1137.17 3264.25,1121.16 3264.25,942.6 3249.9,928.25 3192.73,928.25 v4(3192.05,927.58)
PMIC_ADC_IN2: R30.2 U6.86 | length 97.8
  Top Layer w6.3: U6.86@3490.04,1309.47 3490.04,1364.11 3503.3,1377.37 R30.2@3503.3,1401.78
PMIC_ADC_IN3: R29.2 U6.88 | length 93
  Top Layer w6.3: U6.88@3450.67,1309.47 3450.67,1400.15 R29.2@3452.3,1401.78
PMIC_ADC_IN4: R28.2 U6.90 | length 96.5
  Top Layer w6.3: R28.2@3401.3,1401.78 3401.3,1377.4 3411.3,1367.4 U6.90@3411.3,1309.47
PMIC_ADC_VREF: C515.1 R504.2 R506.2 R519.2 U6.95 | length 1505.3
  Top Layer w11.8: v4(3312.88,1264.94) U6.95@3312.88,1309.47
  SIGNAL 2 w30: v4(3312.88,1264.94) 3312.88,1287.75 3337.16,1312.03 3770.59,1312.03 4104.82,1646.26 4104.82,1800.71 4139.32,1835.21 4266.67,1835.21 4339.44,1907.98 v1(4339.44,1937.63) v1(4339.44,1972.01)
PMIC_AVDD: C601.1 C602.1 L7.2 U6.59 | length 522.1
  Top Layer w11: v4(3709.3,927.58) U6.59@3753.82,927.58
  Top Layer w20: v1(3973.12,895.83) L7.2@4063.07,895.83
  SIGNAL 2 w20: v4(3709.3,927.58) 3722.11,940.39 3823.29,940.39 3880.07,883.6 3960.89,883.6 v1(3973.12,895.83)
  Bottom Layer w20: v1(3973.12,895.83) C602.1@4003.07,895.83 C601.1@4063.07,895.83
PMIC_BEN: L504.1 U6.47 | length 3044
  Top Layer w6.3: U6.47@3627.84,703.17 3627.84,663.55 v4(3637.66,653.73)
  SIGNAL 3 w4.5: v1(2005.84,2261.61) 2063.68,2203.77 2063.68,2185.82 2124.45,2125.05 3082.28,2125.05 3408.71,1798.63 3408.71,1627.88 3477.59,1559 3477.59,1455.08 3487.76,1444.9 3487.76,1254.13 3501.78,1240.12 3519.56,1240.12 3528.63,1231.05 3528.63,1050.89 3546.03,1033.49 3662.78,1033.49 3683.52,1012.75 3683.52,785.13 3637.66,739.27 v4(3637.66,653.73)
  Bottom Layer w6.3: v1(2005.84,2261.61) L504.1@2005.84,2290.45
PMIC_BEN_F: J500.12 L504.2 | length 78.3
  Bottom Layer w6.3: J500.12@1980.62,2393.7 1980.62,2368.41 2005.84,2343.2 L504.2@2005.84,2325.88
PMIC_CMODE: L508.1 U6.39 | length 3874
  Top Layer w6.3: U6.39@3470.36,703.17 v4(3470.36,747.7)
  SIGNAL 3 w4.5: v1(1866.65,2261.61) 1891.9,2286.86 2153.26,2286.86 2175.68,2264.44 3555.99,2264.44 3789.7,2030.73 3789.7,1649.78 3821.23,1618.26 3821.23,743.7 3709.27,631.75 3599.15,631.75 3590.87,640.03 3551.29,640.03 3470.36,720.96 v4(3470.36,747.7)
  Bottom Layer w6.3: v1(1866.65,2261.61) L508.1@1866.65,2290.45
PMIC_CMODE_F: J500.7 L508.2 | length 74.3
  Bottom Layer w6.3: L508.2@1866.65,2325.88 1866.65,2342.97 1882.2,2358.53 J500.7@1882.2,2393.7
PMIC_COMPOUT: U6.12 U9.2 | length 555.3
  Top Layer w6.3: U9.2@2694.46,1063.11 2694.46,1095.97 2698.15,1099.66 2769.2,1099.66 2776.51,1092.35 2776.51,1041.11 2800.45,1017.18 3105.88,1017.18 3114.71,1026 U6.12@3147.52,1026
PMIC_EXT_SMPL: R26.2 U2.M2 U6.37 | length 2049.7
  Top Layer w5.4: 2279.04,1495.9 2304.32,1495.9 U2.M2@2320.07,1480.15
  Top Layer w6.3: R26.2@2157.06,1485.52 2262.44,1485.52 2272.83,1495.9 2279.04,1495.9 ; v2(2304.32,1464.4) U2.M2@2320.07,1480.15 ; U6.37@3430.99,703.17 v4(3430.99,747.7)
  SIGNAL 4 w4.5: v2(2304.32,1464.4) 2320.04,1448.68 2342.28,1448.68 2351.61,1439.35 2351.61,1298.64 2425.34,1224.91 2828.76,1224.91 2890.83,1286.98 3163.56,1286.98 3213.22,1237.32 3213.22,1205.09 3225.24,1193.07 3302.84,1193.07 3316.36,1179.55 3316.36,782.07 3350.73,747.7 v4(3430.99,747.7)
PMIC_GEN: L505.1 U6.46 | length 3004.1
  Top Layer w6.3: v4(3608.15,656.64) U6.46@3608.15,703.17
  SIGNAL 3 w4.5: v1(1971.04,2261.61) 2122.86,2109.79 3062.64,2109.79 3392.12,1780.3 3392.12,1558.19 3431.8,1518.51 3431.8,1461.9 3451.27,1442.43 3451.27,1252.99 3477.54,1226.73 3477.54,998.22 3493.95,981.81 3616.15,981.81 3636.61,961.35 3636.61,785.77 3608.15,757.32 v4(3608.15,656.64)
  Bottom Layer w6.3: v1(1971.04,2261.61) L505.1@1971.04,2290.45
PMIC_GEN_F: J500.11 L505.2 | length 72
  Bottom Layer w6.3: J500.11@1960.94,2393.7 1960.94,2353.8 1971.04,2343.7 L505.2@1971.04,2325.88
PMIC_INTZ: R561.1 U2.E2 U6.10 | length 1901.8
  Top Layer w6.3: v2(2304.32,1684.87) U2.E2@2320.07,1700.62 ; U6.10@3147.52,1065.37 v4(3192.05,1065.37)
  SIGNAL 4 w4.5: v2(2304.32,1684.87) 2247.18,1684.87 2199.72,1637.41 2199.72,1470.45 2168.9,1439.62 2168.9,1209.17 2249.27,1128.79 2622.21,1128.79 2673.89,1077.11 2855.51,1077.11 2860.05,1072.57 2875.08,1072.57 2879.62,1077.11 2915.15,1077.11 2971.03,1132.98 3065.31,1132.98 3093.56,1104.74 3118.18,1104.74 3157.55,1065.37 v4(3192.05,1065.37)
  Bottom Layer w6.3: R561.1@3062.87,1046.6 3066.81,1046.6 3085.59,1065.37 v4(3192.05,1065.37)
PMIC_LED_DEN: R54.2 R530.2 U6.18 | length 1873.9
  Top Layer w6.3: R54.2@3062.87,868.98 3062.87,890.28 3071.22,898.63 3093.73,898.63 v4(3103,907.89) U6.18@3147.52,907.89
  SIGNAL 4 w4.5: v1(2035.02,1664.12) 2035.02,1565.63 2101.41,1499.24 2101.41,1272.92 2082.09,1253.59 2082.09,1056.67 2170.3,968.45 2281.18,968.45 2292.03,957.6 3053.29,957.6 v4(3103,907.89)
  Bottom Layer w6.3: v1(2035.02,1664.12) R530.2@2035.02,1699.32
PMIC_LED_DEN_S: R530.1 U2.H3 | length 498.2
  Top Layer w6.3: U2.H3@2351.57,1606.13 v2(2367.31,1590.38)
  Bottom Layer w5.4: 2241.83,1630.15 2249.87,1622.11 2275.78,1622.11 2291.71,1606.18 2351.52,1606.18 v2(2367.31,1590.38)
  Bottom Layer w6.3: R530.1@1987.78,1699.32 1987.78,1719.93 1994.98,1727.14 2172.36,1727.14 2224.79,1674.71 2224.79,1647.19 2241.83,1630.15
PMIC_LED_SEN: R532.2 R569.2 U6.19 | length 1961.8
  Top Layer w6.3: U6.19@3147.52,888.21 v4(3192.05,888.21)
  SIGNAL 4 w4.5: v1(2110.32,1662.53) 2133.76,1639.1 2133.76,1173.58 2319.91,987.42 2901.95,987.42 2934.15,1019.62 2984.48,1019.62 2994.02,1029.16 3087.53,1029.16 3143.97,972.71 3143.97,901.78 3157.55,888.21 v4(3192.05,888.21)
  Bottom Layer w6.3: R532.2@2110.32,1629.72 v1(2110.32,1662.53) ; R569.2@3066.81,868.98 3086.04,888.21 v4(3192.05,888.21)
PMIC_LED_SEN_S: R532.1 U2.J2 | length 232.1
  Top Layer w6.3: U2.J2@2320.07,1574.64 v2(2335.82,1590.38)
  Bottom Layer w6.3: R532.1@2157.57,1629.72 2185.61,1629.72 2243.4,1571.93 2317.37,1571.93 v2(2335.82,1590.38)
PMIC_LEDSEL_0: C510.1 J2.1 R510.2 R521.2 U14.1 | length 4739.9
  Top Layer w6.3: v1(1079.84,2362.1) J2.1@1079.84,2411.61 ; v1(2612.12,737.89) U14.1@2657.68,737.89
  SIGNAL 1 w4.5: v1(1079.84,2362.1) 1079.16,2362.78 1037.46,2362.78 946.63,2271.94 946.63,2059.95 910.15,2023.48 910.15,1384.89 1180.23,1114.81 1281.99,1114.81 1439.36,957.44 1784.93,957.44 1879.75,862.62 1980.68,862.62 2041.37,923.31 2192.32,923.31 2329.57,786.06 2563.96,786.06 v1(2612.12,737.89)
  SIGNAL 2 w4.5: v1(1079.84,2362.1) 1144.03,2426.29 1568.44,2426.29 1756.17,2238.57 1987.58,2238.57 2057.33,2168.81 2057.33,1976.8 v1(2119.81,1914.32)
  Bottom Layer w6.3: C510.1@1058.12,2411.61 1058.12,2383.82 v1(1079.84,2362.1) ; v1(2119.81,1914.32) R510.2@2152.78,1914.32 R521.2@2152.78,1845.56
PMIC_LEDSEL_0_S: R521.1 U2.F4 | length 283.8
  Top Layer w6.3: v2@2367.4,1684.7 U2.F4@2382.97,1669.12
  Bottom Layer w5.4: 2313.47,1708.29 2321.23,1700.53 2342.32,1700.53 2342.36,1700.57 2351.61,1700.57
  Bottom Layer w5.5: 2351.61,1700.57 2367.31,1684.87 v2(2367.31,1684.7)
  Bottom Layer w6.3: R521.1@2152.78,1798.32 2223.45,1798.32 2313.47,1708.29
PMIC_LEDSEL_1: C509.1 J2.2 R8.2 R12.2 U14.4 | length 4854.7
  Top Layer w6.3: v1(1119.21,2362.1) J2.2@1119.21,2411.61 ; v1(2122.81,1845.56) R12.2@2152.78,1845.56 R8.2@2152.78,1914.32 ; U14.4@2657.68,661.12 v1(2703.24,661.12)
  SIGNAL 1 w4.5: v1(1119.21,2362.1) 1151.65,2329.66 1151.65,2274.87 1043.17,2166.38 1043.17,2128.43 927.65,2012.92 927.65,1383.95 1185.08,1126.52 1286.84,1126.52 1444.21,969.15 1789.78,969.15 1884.6,874.33 1975.83,874.33 2036.52,935.02 2201.39,935.02 2338.64,797.77 2590.03,797.77 2703.24,684.56 v1(2703.24,661.12)
  SIGNAL 2 w4.5: v1(1119.21,2362.1) 1163.22,2406.11 1565.18,2406.11 1752.86,2218.43 1969.71,2218.43 2042,2146.15 2042,1959.74 2075.82,1925.92 2075.82,1892.55 v1(2122.81,1845.56)
  Bottom Layer w6.3: C509.1@1106.42,2411.61 1106.42,2374.88 v1(1119.21,2362.1)
PMIC_LEDSEL_1_S: R12.1 U2.E1 | length 197.7
  Top Layer w5.75: 2270.12,1691.08 2279.03,1691.08 U2.E1@2288.57,1700.62
  Top Layer w6.3: R12.1@2152.78,1798.32 2152.78,1775.19 2236.9,1691.08 2270.12,1691.08
PMIC_LEDSEL_2: C508.1 J2.3 R511.2 R522.2 U14.9 | length 4735.5
  Top Layer w6.3: v1(1158.58,2362.1) J2.3@1158.58,2411.61 ; v1(2844.41,609.94) U14.9@2889.97,609.94
  SIGNAL 1 w4.5: v1(1158.58,2362.1) 1158.58,2339.58 1168.39,2329.77 1168.39,2272.31 1109.98,2213.9 1109.98,2173.29 945.8,2009.1 945.8,1566.04 996.68,1515.15 996.68,1332.89 1190.35,1139.23 1292.1,1139.23 1449.47,981.86 1795.04,981.86 1889.86,887.04 1970.57,887.04 2031.26,947.72 2213.39,947.72 2350.64,810.48 2615.78,810.48 2816.31,609.94 v1(2844.41,609.94)
  SIGNAL 2 w4.5: v1(1158.58,2362.1) 1183.14,2386.66 1559.44,2386.66 1752.95,2193.15 1853.91,2193.15 2026.81,2020.25 2026.81,1932.32 v1(2044.81,1914.32)
  Bottom Layer w6.3: C508.1@1154.73,2411.61 1158.58,2407.77 v1(1158.58,2362.1) ; v1(2044.81,1914.32) R511.2@2077.78,1914.32 R522.2@2077.78,1845.56
PMIC_LEDSEL_2_S: R522.1 U2.F2 | length 344.3
  Top Layer w6.3: U2.F2@2320.07,1669.12 v2(2335.82,1653.38)
  Bottom Layer w6.3: R522.1@2077.78,1794.38 R522.1@2077.78,1798.32 2108.65,1767.45 2190.3,1767.45 2304.38,1653.38 v2(2335.82,1653.38)
PMIC_LEDSEL_3: C507.1 J2.4 R7.2 R11.2 U14.12 | length 4752.1
  Top Layer w6.3: v1(1197.95,2362.1) J2.4@1197.95,2411.61 ; v1(2047.81,1845.56) R11.2@2077.78,1845.56 R7.2@2077.78,1914.32 ; U14.12@2889.97,686.71 v1(2935.52,686.71)
  SIGNAL 1 w4.5: v1(1197.95,2362.1) 1197.95,2337.14 1186.31,2325.51 1186.31,2268.93 1124.53,2207.15 1124.53,2169.34 969.86,2014.68 969.86,1586.77 1016.28,1540.35 1016.28,1330.91 1195.51,1151.69 1297.26,1151.69 1454.63,994.31 1800.2,994.31 1895.02,899.5 1965.41,899.5 2026.1,960.18 2221.37,960.18 2358.62,822.94 2647.69,822.94 2783.91,686.71 v1(2935.52,686.71)
  SIGNAL 2 w4.5: v1(1197.95,2362.1) 1231.88,2328.17 1589.79,2328.17 1856.02,2061.93 1933.1,2061.93 1957.42,2037.61 1957.42,1966.56 2047.81,1876.17 v1(2047.81,1845.56)
  Bottom Layer w6.3: v1(1197.95,2362.1) 1197.95,2379.72 1208.04,2389.81 C507.1@1208.04,2411.61
PMIC_LEDSEL_3_s: R11.1 U2.F1 | length 264.3
  Top Layer w6.3: R11.1@2077.78,1798.32 2115.88,1760.22 2138.32,1760.22 2229.41,1669.12 U2.F1@2288.57,1669.12
PMIC_LM3409_DRVEN: L510.1 U6.38 U10.4 | length 3445.3
  Top Layer w6.3: U10.4@2895.75,1063.11 2899.47,1066.83 v1(2899.47,1106.18) ; v4(3450.67,658.64) U6.38@3450.67,703.17
  SIGNAL 2 w4.5: v1(2899.47,1106.18) 2899.47,1070.94 2955.78,1014.63 3105.43,1014.63 3151.78,968.29 3151.78,667.82 3190.24,629.36 3421.39,629.36 v4(3450.67,658.64)
  SIGNAL 3 w4.5: v1(1797.05,2261.61) 1769.41,2289.26 1747.87,2289.26 1731.93,2273.32 1731.93,2254.81 1822.43,2164.32 1822.43,2145.81 1907.26,2060.97 1968.49,2060.97 2065.16,1964.31 2906.68,1964.31 3013.1,1857.88 3013.1,1609.45 3028.7,1593.85 3028.7,1447.71 2980.42,1399.43 2980.42,1196.9 2936.63,1153.11 2936.63,1143.34 v1(2899.47,1106.18)
  Bottom Layer w6.3: v1(1797.05,2261.61) L510.1@1797.05,2290.45
PMIC_LM3409_DRVEN_F: J500.3 L510.2 | length 70.5
  Bottom Layer w6.3: L510.2@1797.05,2325.88 1797.05,2348.3 1803.46,2354.71 J500.3@1803.46,2393.7
PMIC_LM3409_IADJ: L500.1 U6.77 | length 2478.3
  Top Layer w6.3: v4(3667.21,1264.94) U6.77@3667.21,1309.47
  SIGNAL 3 w4.5: v1(2145.03,2261.48) 2157.79,2248.71 3373.86,2248.71 3697.95,1924.63 3697.95,1564.37 3746.35,1515.96 3746.35,1344.08 v4(3667.21,1264.94)
  Bottom Layer w6.3: v1(2145.03,2261.48) L500.1@2145.03,2290.32
PMIC_LM3409_IADJ_F: J500.19 L500.2 | length 79
  Bottom Layer w6.3: J500.19@2118.42,2393.7 2118.42,2368.15 2145.03,2341.54 L500.2@2145.03,2325.76
PMIC_LM3409_SYNC: L511.1 U6.15 | length 2469.8
  Top Layer w6.3: U6.15@3147.52,966.95 v4(3192.05,966.95)
  SIGNAL 3 w4.5: v1(1762.42,2261.61) 1762.42,2261.44 1787.52,2236.35 1813.9,2236.35 2008.4,2041.85 2852.29,2041.85 3070.91,1823.23 3070.91,1576.81 3143.72,1504 3143.72,1058.64 3192.05,1010.31 v4(3192.05,966.95)
  Bottom Layer w6.3: v1@1762.34,2261.69 L511.1@1762.34,2290.37
PMIC_LM3409_SYNC_F: J500.1 L511.2 | length 68.6
  Bottom Layer w6.3: L511.2@1762.26,2325.88 1762.26,2358.4 1764.09,2360.23 J500.1@1764.09,2393.7
PMIC_LS_SENSE_N: L501.1 U6.82 | length 2386
  Top Layer w6.3: U6.82@3568.78,1309.47 v4(3568.78,1354)
  SIGNAL 3 w4.5: v1(2110.23,2261.61) 2130.55,2241.29 2130.55,2220.7 2176.67,2174.59 3378.5,2174.59 3685.71,1867.37 3685.71,1470.92 v4(3568.78,1354)
  Bottom Layer w6.3: v1(2110.23,2261.61) L501.1@2110.23,2290.45
PMIC_LS_SENSE_N_F: J500.17 L501.2 | length 86.4
  Bottom Layer w6.3: J500.17@2079.05,2393.7 2079.05,2369.26 2090.8,2357.51 2100.54,2357.51 2110.23,2347.82 L501.2@2110.23,2325.88
PMIC_LS_SENSE_P: L502.1 U6.83 | length 2271.3
  Top Layer w6.3: v4(3549.1,1264.94) U6.83@3549.1,1309.47
  SIGNAL 3 w4.5: v1(2075.43,2261.61) 2114.85,2222.19 2114.85,2216.91 2175.1,2156.66 3149.47,2156.66 3571.31,1734.82 3571.31,1529.6 3547.08,1505.38 3547.08,1304.98 3549.1,1302.97 v4(3549.1,1264.94)
  Bottom Layer w6.3: v1(2075.43,2261.61) L502.1@2075.43,2290.45
PMIC_LS_SENSE_P_F: J500.16 L502.2 | length 74.5
  Bottom Layer w6.3: J500.16@2059.36,2393.7 2059.36,2359.68 2075.43,2343.61 L502.2@2075.43,2325.88
PMIC_PARKZ: R559.2 U2.E4 U6.8 | length 2855.7
  Top Layer w6.3: v2(2367.31,1716.37) U2.E4@2383.06,1700.62 ; U6.8@3147.52,1104.74 v4(3192.05,1104.74)
  SIGNAL 1 w4.5: v2(2367.31,1716.37) 2351.58,1700.63 2241.32,1700.63 2147.97,1607.28 2012.18,1607.28 1958.4,1661.07 1848.79,1661.07 1807.27,1619.55 1807.27,1558.96 1772.56,1524.25 1772.56,1259.68 1894.7,1137.54 2672.55,1137.54 2743.42,1066.67 2892.97,1066.67 2961.48,1135.18 2983.56,1135.18 3073.34,1224.96 3113.54,1224.96 3143.97,1194.53 3143.97,1152.82 v4(3192.05,1104.74)
  Bottom Layer w6.3: R559.2@3061.36,1104.74 v4(3192.05,1104.74)
PMIC_R_IADJ: R27.2 U6.76 | length 94.7
  Top Layer w6.3: U6.76@3686.84,1309.52 R27.2@3686.84,1404.2
PMIC_REN: L506.1 U6.45 | length 2895.7
  Top Layer w6.3: U6.45@3588.47,703.17 v4(3588.47,747.7)
  SIGNAL 3 w4.5: v1(1936.24,2261.61) 1943.01,2261.61 2113.34,2091.28 2879.99,2091.28 2910.41,2060.85 3081.55,2060.85 3373.65,1768.75 3373.65,1410.26 3409.74,1374.17 3409.74,1249.89 3424.06,1235.58 3424.06,944.66 3442.79,925.93 3563.61,925.93 3588.47,901.07 v4(3588.47,747.7)
  Bottom Layer w6.3: v1(1936.24,2261.61) L506.1@1936.24,2290.45
PMIC_REN_F: J500.10 L506.2 | length 69.9
  Bottom Layer w6.3: L506.2@1936.24,2325.88 1936.24,2349.48 1941.25,2354.49 J500.10@1941.25,2393.7
PMIC_SEN1: L509.1 U6.43 | length 2933.2
  Top Layer w6.3: U6.43@3549.1,703.17 v4(3549.1,747.7)
  SIGNAL 3 w4.5: v1(1831.85,2261.61) 1831.85,2258.3 1993.31,2096.83 2010.32,2096.83 2049.14,2058.01 2859.26,2058.01 3088.55,1828.71 3088.55,1590.01 3189.4,1489.16 3189.4,1341.68 3212.06,1319.02 3295.65,1319.02 3333.16,1281.51 3333.16,1247.02 3319.6,1233.46 3319.6,837.28 3336.41,820.47 3460.78,820.47 3479.65,801.6 3479.65,787.73 3495.74,771.64 3524.94,771.64 v4@3548.89,747.7
  Bottom Layer w6.3: v1(1831.85,2261.61) L509.1@1831.85,2290.45
PMIC_SEN1_F: J500.5 J500.6 L509.2 | length 92
  Bottom Layer w6.3: L509.2@1831.85,2325.88 1831.85,2348.09 1842.83,2359.07 J500.5@1842.83,2393.7 J500.6@1862.51,2393.7
PMIC_SEN2: L507.1 U6.44 | length 3001.6
  Top Layer w6.3: v4(3568.78,658.64) U6.44@3568.78,703.17
  SIGNAL 3 w4.5: v1(1901.45,2261.61) 2005.34,2157.72 2026.93,2157.72 2110.77,2073.87 2867.94,2073.87 2901.59,2040.22 3069.36,2040.22 3350.88,1758.71 3350.88,1322.26 3374.41,1298.73 3374.41,887.53 3388.13,873.81 3514.6,873.81 3528.6,859.81 3528.6,789.16 3549.08,768.67 3559.53,768.67 3568.78,759.42 v4(3568.78,658.64)
  Bottom Layer w6.3: v1(1901.45,2261.61) L507.1@1901.45,2290.45
PMIC_SEN2_F: J500.8 J500.9 L507.2 | length 87.1
  Bottom Layer w6.3: L507.2@1901.45,2325.88 J500.8@1901.45,2393.26 ; J500.8@1901.88,2393.7 J500.9@1921.57,2393.7
PMIC_SEQ_STRT: R19.2 R47.2 U6.7 U6.16 | length 1972.2
  Top Layer w6.3: v1(2071.77,1631.74) 2072.78,1630.73 2109.31,1630.73 R19.2@2110.32,1629.72 ; R47.2@3062.87,1105.2 3066.81,1105.2 3086.04,1124.43 v4(3103,1124.43) U6.7@3147.52,1124.43 ; v4(3103,947.26) U6.16@3147.52,947.26
  SIGNAL 1 w4.5: v4(3103,947.26) 3130.21,974.48 3130.21,1097.21 v4(3103,1124.43)
  SIGNAL 4 w4.5: v1(2071.77,1631.74) 2118.7,1584.81 2118.7,1155.95 2301.7,972.95 2924.93,972.95 2961.08,1009.1 3041.16,1009.1 v4(3103,947.26)
PMIC_SEQ_STRT_S: R19.1 U2.J1 | length 153.8
  Top Layer w6.3: R19.1@2157.57,1629.72 2203.31,1629.72 2249.72,1583.31 2279.9,1583.31 U2.J1@2288.57,1574.64
PMIC_SPI2_CLK: R579.2 R586.2 U6.34 U513.1 | length 617.7
  Top Layer w6.3: U6.34@3371.93,703.17 3371.93,660.95 3381.85,651.03 3381.85,530.2 3417.65,494.4 3456.86,494.4 3499.97,451.29 v1(3499.97,388.98)
  Bottom Layer w6.3: U513.1@3478.26,388.98 v1(3499.97,388.98) 3595.89,388.98 ; 3602.85,383.2 3602.85,393.2 ; R586.2@3607.2,355.42 3607.2,377.67 ; R579.2@3607.2,423.3 3607.2,400.29 ; 3595.89,388.98 3607.2,400.29 ; 3595.89,388.98 3607.2,377.67 ; 3607.2,377.67 3607.2,400.29
PMIC_SPI2_CLK_S: C627.1 J16.7 R586.1 | length 279.7
  Bottom Layer w6.3: R586.1@3607.2,308.17 3607.2,282.72 3612.61,277.31 3612.61,179.61 J16.7@3663.48,128.74 C627.1@3663.48,51.8
PMIC_SPI2_CSZ: R588.2 R590.1 | length 58.8
  Bottom Layer w6.3: R588.2@3719.2,355.41 R590.1@3778.03,355.39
